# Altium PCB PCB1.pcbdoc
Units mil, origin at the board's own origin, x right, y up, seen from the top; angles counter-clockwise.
Board outline 2485 x 3040 mil, 2 copper layers (Top Layer, Bottom Layer); 17 components, 31 nets, 146 pads, 1 vias.
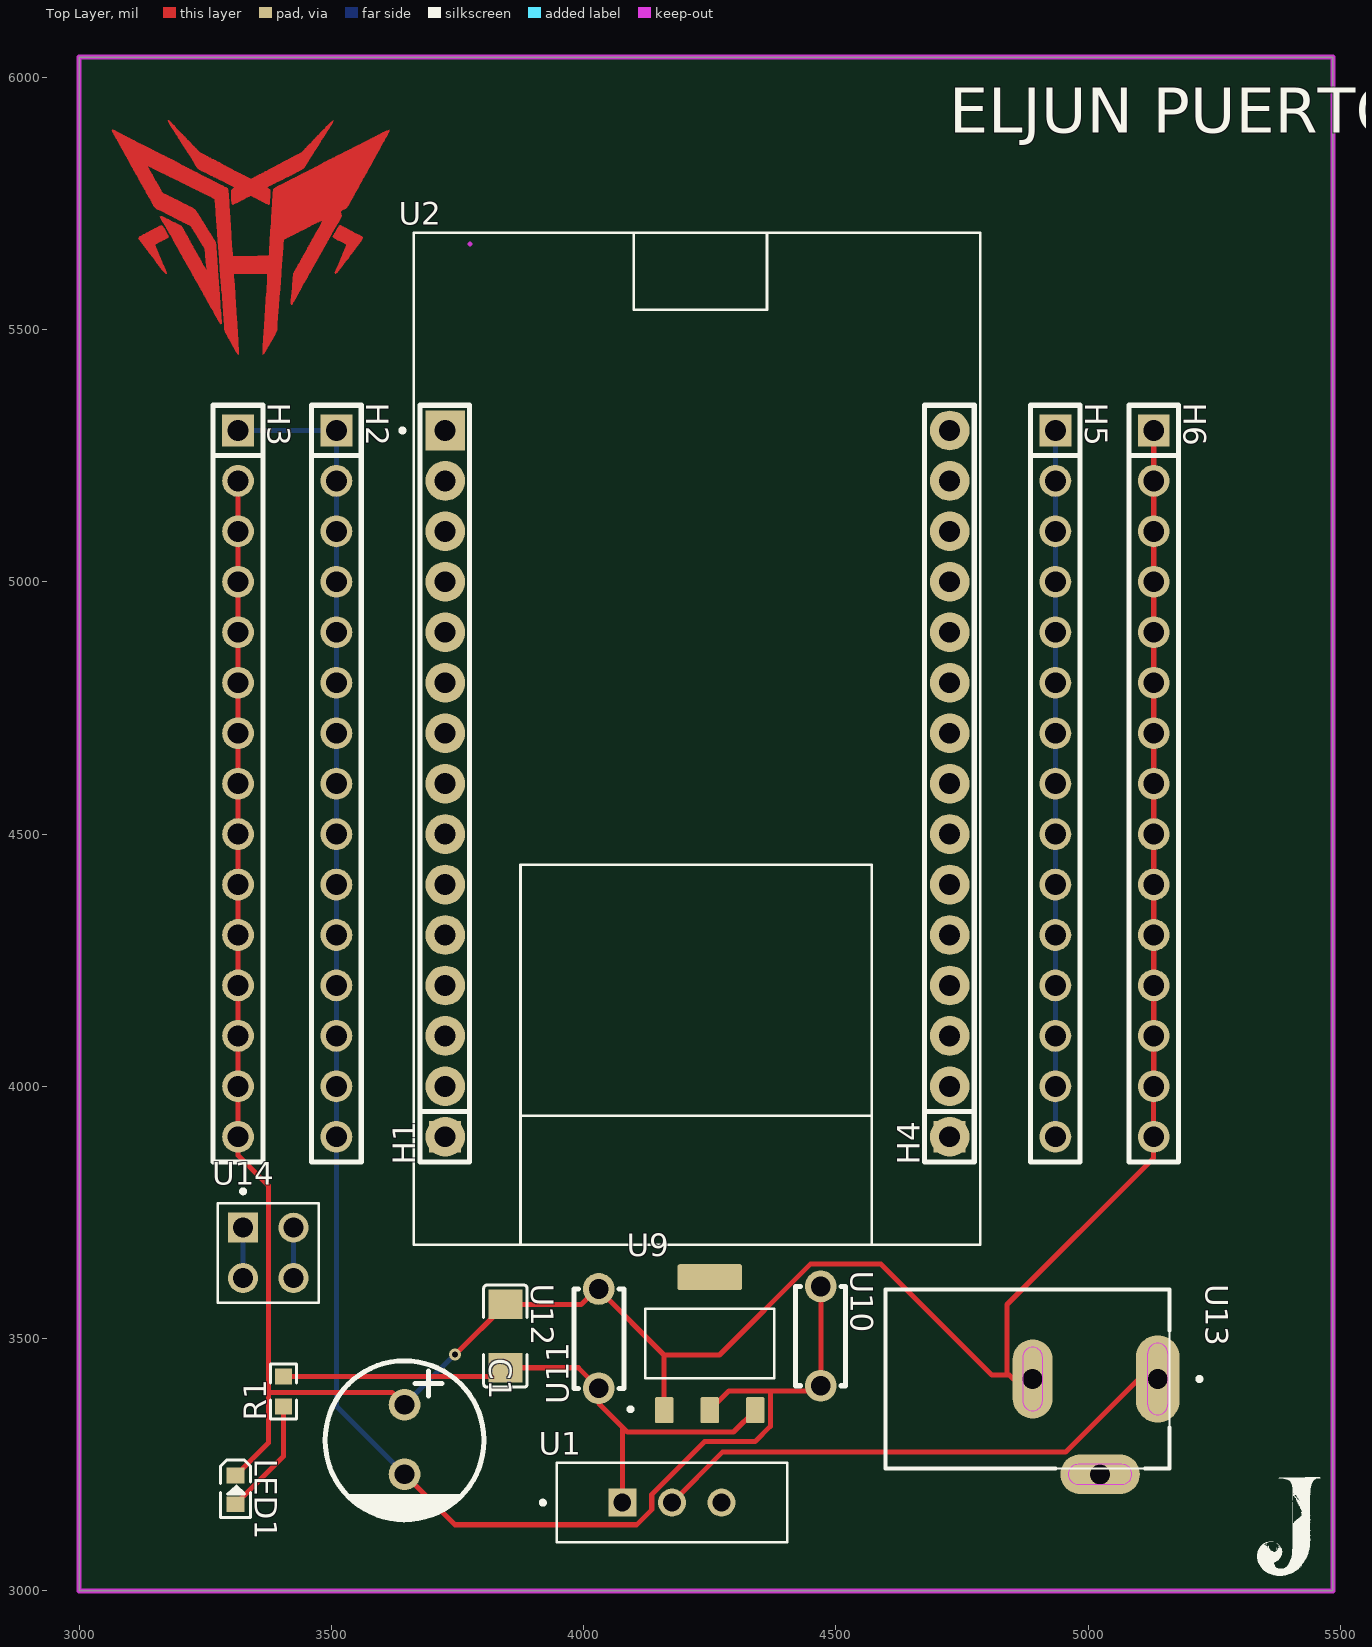
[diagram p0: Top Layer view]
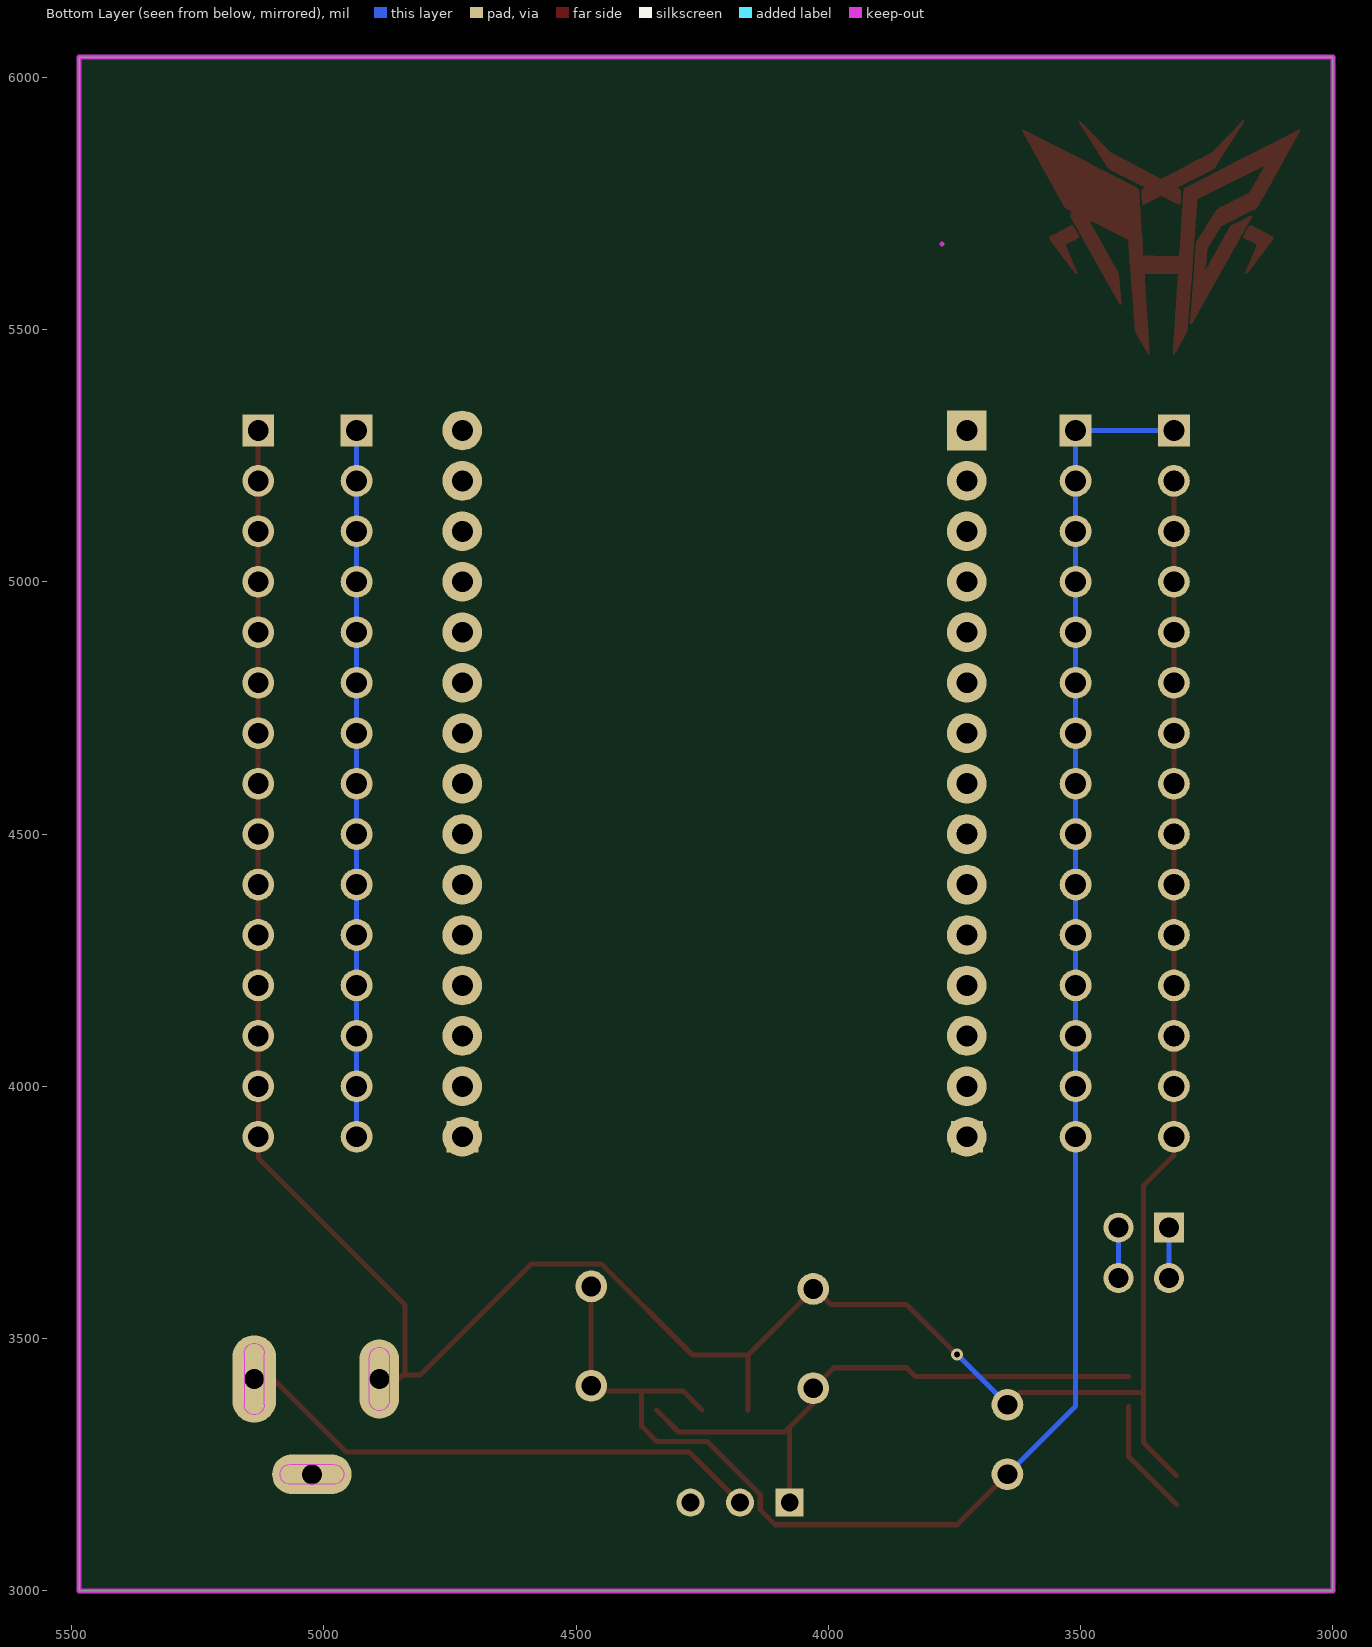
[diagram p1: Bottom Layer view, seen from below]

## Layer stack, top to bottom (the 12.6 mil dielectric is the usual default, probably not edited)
Top Layer: signal copper (thickness not stored)
Dielectric: dielectric 12.6, FR-4, Dk 4.8
Bottom Layer: signal copper (thickness not stored)

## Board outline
3000,6040 5485,6040 5485,3000 3000,3000

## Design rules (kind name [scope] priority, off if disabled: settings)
BoardOutlineClearance copperThickness1oz [All] p0: genericclearance=10 ignorepadtopadclearanceinfootprint=FALSE except(0: Arc-SplitContinuation Track-SplitContinuation SMDPad-SplitContinuation THPad-SplitContinuation Via-SplitContinuation Fill-SplitContinuation Poly-SplitContinuation Region-SplitContinuation Text-SplitContinuation; 6: Track-CutoutEdge SMDPad-CutoutEdge THPad-CutoutEdge Via-CutoutEdge Region-CutoutEdge; 11.8: Track-OutlineEdge SMDPad-OutlineEdge THPad-OutlineEdge Via-OutlineEdge Fill-OutlineEdge Region-OutlineEdge Poly-OutlineEdge Text-OutlineEdge Fill-CutoutEdge)
BoardOutlineClearance copperThickness2oz [All] p0: genericclearance=10 ignorepadtopadclearanceinfootprint=FALSE except(0: Arc-SplitContinuation Track-SplitContinuation SMDPad-SplitContinuation THPad-SplitContinuation Via-SplitContinuation Fill-SplitContinuation Poly-SplitContinuation Region-SplitContinuation Text-SplitContinuation; 6: Track-CutoutEdge SMDPad-CutoutEdge THPad-CutoutEdge Via-CutoutEdge Region-CutoutEdge; 11.8: Track-OutlineEdge SMDPad-OutlineEdge THPad-OutlineEdge Via-OutlineEdge Fill-OutlineEdge Region-OutlineEdge Poly-OutlineEdge Text-OutlineEdge Fill-CutoutEdge)
Clearance copperThickness1oz [(InNet('+5V') OR InNet('GND') OR InNet('EN') OR InNet('VP') OR InNet('VN') OR InNet('D2') OR InNet('D4') OR InNet('D5') OR InNet('D12') OR InNet('D14') OR InNet('D15') OR InNet('D18') OR InNet('D19') OR InNet('D21') OR InNet('+3V3') OR InNet('RX0') OR InNet('TX0') OR InNet('RX2') OR InNet('TX2') OR InNet('D22') OR InNet('D23') OR InNet('D25') OR InNet('D26') OR InNet('D27') OR InNet('D32') OR InNet('D33') OR InNet('D35') OR InNet('D34') OR InNet('$1N2884') OR InNet('VCC') OR InNet('$1N2361'))] p1: gap=7 ignorepadtopadclearanceinfootprint=FALSE except(4: Track-Track; 6: Track-SMDPad SMDPad-SMDPad Track-THPad SMDPad-THPad THPad-THPad Track-Via SMDPad-Via THPad-Via Via-Via SMDPad-Fill THPad-Fill Via-Fill Fill-Fill Track-Region SMDPad-Region THPad-Region Via-Region Region-Region Track-Poly SMDPad-Poly THPad-Poly Via-Poly Fill-Poly Region-Poly Poly-Poly Track-Text SMDPad-Text THPad-Text Via-Text Fill-Text Region-Text Poly-Text Text-Text; 6.9: Track-Hole SMDPad-Hole THPad-Hole Via-Hole Fill-Hole Region-Hole Poly-Hole Text-Hole Sheet-Hole; 11.8: Track-Fill Fill-Region Track-Sheet SMDPad-Sheet THPad-Sheet Via-Sheet Fill-Sheet Region-Sheet Poly-Sheet Text-Sheet)
Clearance copperThickness2oz [All] p1: gap=7 ignorepadtopadclearanceinfootprint=FALSE except(6: Track-SMDPad SMDPad-SMDPad Track-THPad SMDPad-THPad THPad-THPad Track-Via SMDPad-Via THPad-Via Via-Via SMDPad-Fill THPad-Fill Via-Fill Fill-Fill Track-Region SMDPad-Region THPad-Region Via-Region Region-Region Track-Poly SMDPad-Poly THPad-Poly Via-Poly Fill-Poly Region-Poly Poly-Poly Track-Text SMDPad-Text THPad-Text Via-Text Fill-Text Region-Text Poly-Text Text-Text; 6.9: Track-Hole SMDPad-Hole THPad-Hole Via-Hole Fill-Hole Region-Hole Poly-Hole Text-Hole Sheet-Hole; 8: Track-Track; 11.8: Track-Fill Fill-Region Track-Sheet SMDPad-Sheet THPad-Sheet Via-Sheet Fill-Sheet Region-Sheet Poly-Sheet Text-Sheet)
DiffPairsRouting differentialPair [All] p1: maxuncoupledlength=10 minlimit=6 maxlimit=6 mostfreqgap=6 toplayer_minwidth=5 toplayer_prefwidth=10 toplayer_maxwidth=100 bottomlayer_minwidth=5 bottomlayer_prefwidth=10 bottomlayer_maxwidth=100
PasteMaskExpansion pasteMaskExpansion [All] p1: expansion=0
PlaneConnect innerPlane [All] p1: planeconnectstyle=Relief reliefexpansion=20 reliefentries=4 reliefconductorwidth=10 reliefairgap=10
PolygonConnect copperRegion [All] p1: connectstyle=Relief reliefentries=4 reliefconductorwidth=10 polygonreliefangle="90 Angle" airgapwidth=10
RoutingVias viaSize [All] p1: viastyle="Through Hole" holewidth=12.0078 minholewidth=11.811 maxholewidth=248.0314 width=24.0158 minwidth=19.685 maxwidth=393.7008
SolderMaskExpansion solderMaskExpansion [All] p1: useseparateexpansions=TRUE expansion=2 expansionbottom=2
Width copperThickness1oz [All] p1: maxlimit=100 minlimit=5 preferedwidth=10
Width copperThickness2oz [All] p1: maxlimit=100 minlimit=8 preferedwidth=10

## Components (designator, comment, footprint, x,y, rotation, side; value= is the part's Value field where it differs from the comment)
C1 "100uF" CAP-TH_BD8.0-P3.50-D0.6-FD_1 3645,3300 r270 top
H1 "HDR-M_2.54_1x15P" HDR-TH_15P-P2.54-V-M 3725,4600 r90 top
H2 "HDR-M_2.54_1x15P" HDR-TH_15P-P2.54-V-M 3510,4600 r270 top
H3 "HDR-M_2.54_1x15P" HDR-TH_15P-P2.54-V-M 3315,4600 r270 top
H4 "HDR-M_2.54_1x15P" HDR-TH_15P-P2.54-V-M 4725,4600 r90 top
H5 "HDR-M_2.54_1x15P" HDR-TH_15P-P2.54-V-M 4935,4600 r270 top
H6 "HDR-M_2.54_1x15P" HDR-TH_15P-P2.54-V-M 5130,4600 r270 top
LED1 "19-217/BHC-ZL1M2RY/3T" LED0603-FD_BLUE 3310,3200 r270 top
R1 "Res_0603" R0603 3405,3395 r90 top
U1 "MINI-SPDT-SW" SW_MINI-SPDT-SW 4175,3175 r0 top
U2 "ESP32-DEVKIT-V1" MODULE_ESP32_DEVKIT_V1 4225.64,4689.15 r0 top
U9 "AMS1117-5.0" SOT229P700X180-4N 4250,3490 r0 top
U10 "100nF" CAP-TH_L5.0-W2.5-P5.00-D1.0 4470,3505 r270 top
U11 "100nF" CAP-TH_L5.0-W2.5-P5.00-D1.0 4030,3500 r90 top
U12 "10nF" C1206 3845,3505 r270 top
U13 "DCJ200-10-A-XX-K_REVA" GCT_DCJ200-10-A-XX-K_REVA 4880,3420 r270 top
U14 "826656-2" TE_826656-2 3375,3670 r0 top

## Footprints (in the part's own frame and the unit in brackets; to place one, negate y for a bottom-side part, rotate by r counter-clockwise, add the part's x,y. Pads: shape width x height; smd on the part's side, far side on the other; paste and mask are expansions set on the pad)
C1206 [mm]
  rect 1.485x1.728 smd: 1(-1.593,0) 2(1.593,0)
  silkscreen extent -2.56,-1.09 2.56,1.09
CAP-TH_BD8.0-P3.50-D0.6-FD_1 [mm]
  round 1.6 hole 1: 1(-1.75,0) 2(1.75,0)
  silkscreen extent -3.96,-4 4.04,4
CAP-TH_L5.0-W2.5-P5.00-D1.0 [mm]
  round 1.6 hole 1: 1(-2.5,0) 2(2.5,0)
  silkscreen extent -2.5,-1.27 2.5,1.25
GCT_DCJ200-10-A-XX-K_REVA [mm]
  oval 4.4x2.2 hole 1: 1(0,6.55)
  oval 4x2 hole 1: 2(0,0.25)
  oval 2x4 hole 1: 3(4.8,3.65)
  Board Outline Layer lines w0.003: 1.1,-0.25 -1.1,-0.25 ; 1.1,-0.25 -1.1,-0.25 ; 1.1,-0.25 ccw(c1.1,0.25) 1.6,0.25 ; 1.1,-0.25 ccw(c1.1,0.25) 1.6,0.25 ; -1.1,-0.25 cw(c-1.1,0.25) -1.6,0.25 ; -1.1,-0.25 cw(c-1.1,0.25) -1.6,0.25 ; 1.6,0.25 ccw(c1.1,0.25) 1.1,0.75 ; 1.6,0.25 ccw(c1.1,0.25) 1.1,0.75 ; -1.6,0.25 cw(c-1.1,0.25) -1.1,0.75 ; -1.6,0.25 cw(c-1.1,0.25) -1.1,0.75 ; 1.1,0.75 -1.1,0.75 ; 1.1,0.75 -1.1,0.75 ; 4.8,2.05 cw(c4.8,2.55) 4.3,2.55 ; 4.8,2.05 cw(c4.8,2.55) 4.3,2.55 ; 4.8,2.05 ccw(c4.8,2.55) 5.3,2.55 ; 4.8,2.05 ccw(c4.8,2.55) 5.3,2.55 ; 5.3,2.55 5.3,4.75 ; 5.3,2.55 5.3,4.75 ; 4.3,2.55 4.3,4.75 ; 4.3,2.55 4.3,4.75 ; 5.3,4.75 ccw(c4.8,4.75) 4.8,5.25 ; 5.3,4.75 ccw(c4.8,4.75) 4.8,5.25 ; 4.3,4.75 cw(c4.8,4.75) 4.8,5.25 ; 4.3,4.75 cw(c4.8,4.75) 4.8,5.25 ; 1.3,6.05 ccw(c1.3,6.55) 1.8,6.55 ; 1.3,6.05 ccw(c1.3,6.55) 1.8,6.55 ; 1.3,6.05 -1.3,6.05 ; 1.3,6.05 -1.3,6.05 ; -1.3,6.05 cw(c-1.3,6.55) -1.8,6.55 ; -1.3,6.05 cw(c-1.3,6.55) -1.8,6.55 ; 1.8,6.55 ccw(c1.3,6.55) 1.3,7.05 ; 1.8,6.55 ccw(c1.3,6.55) 1.3,7.05 ; -1.8,6.55 cw(c-1.3,6.55) -1.3,7.05 ; -1.8,6.55 cw(c-1.3,6.55) -1.3,7.05 ; 1.3,7.05 -1.3,7.05 ; 1.3,7.05 -1.3,7.05
  silkscreen extent -4.5,-7.15 4.5,8.75
HDR-TH_15P-P2.54-V-M [mm]
  rect 1.6x1.6 hole 1.05: 1(-17.78,0)
  round 1.6 hole 1.05: 2(-15.24,0) 3(-12.7,0) 4(-10.16,0) 5(-7.62,0) 6(-5.08,0) 7(-2.54,0) 8(0,0) 9(2.54,0) 10(5.08,0) 11(7.62,0) 12(10.16,0) 13(12.7,0) 14(15.24,0) 15(17.78,0)
  silkscreen extent -19.05,-1.25 19.05,1.25
LED0603-FD_BLUE [mm]
  rect 0.8x0.9 smd: 1(-0.72,0) 2(0.72,0)
  silkscreen extent -1.5,-0.76 1.38,0.76
MODULE_ESP32_DEVKIT_V1 [mm]
  rect 2x2 hole 1.02: 1(-12.7,15.515)
  round 2 hole 1.02: 2(-12.7,12.975) 3(-12.7,10.435) 4(-12.7,7.895) 5(-12.7,5.355) 6(-12.7,2.815) 7(-12.7,0.275) 8(-12.7,-2.265) 9(-12.7,-4.805) 10(-12.7,-7.345) 11(-12.7,-9.885) 12(-12.7,-12.425) 13(-12.7,-14.965) 14(-12.7,-17.505) 15(-12.7,-20.045) 16(12.7,-20.045) 17(12.7,-17.505) 18(12.7,-14.965) 19(12.7,-12.425) 20(12.7,-9.885) 21(12.7,-7.345) 22(12.7,-4.805) 23(12.7,-2.265) 24(12.7,0.275) 25(12.7,2.815) 26(12.7,5.355) 27(12.7,7.895) 28(12.7,10.435) 29(12.7,12.975) 30(12.7,15.515)
  silkscreen extent -14.95,-25.48 14.23,25.48
R0603 [mil]
  rect 31.75x34.02 smd: 1(-29.66,0) 2(29.66,0)
  silkscreen extent -55,-26 55,26
SOT229P700X180-4N [mm]
  rrect15% 0.93x1.31 smd: 1(-2.29,-3.345) 2(0,-3.345) 3(2.29,-3.345)
  rrect15% 3.24x1.31 smd: 4(0,3.345)
  silkscreen extent -4.09,-3.4 3.25,1.75
SW_MINI-SPDT-SW [mm]
  rect 1.408x1.408 hole 0.9: 1(-2.5,0)
  round 1.408 hole 0.9: 2(0,0) 3(2.5,0)
  silkscreen extent -6.6,-2 5.8,2
TE_826656-2 [mm]
  rect 1.508x1.508 hole 1: 1(-1.27,1.27)
  round 1.508 hole 1: 2(1.27,1.27) 3(-1.27,-1.27) 4(1.27,-1.27)
  silkscreen extent -2.54,-2.5 2.54,3.2

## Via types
v1: diameter 24.02, hole 12.01, Top Layer to Bottom Layer, 1 vias

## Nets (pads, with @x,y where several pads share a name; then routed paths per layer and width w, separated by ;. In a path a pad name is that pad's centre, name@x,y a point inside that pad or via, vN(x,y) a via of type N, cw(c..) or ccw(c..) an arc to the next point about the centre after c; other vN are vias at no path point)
$1N2361: U1.2 U13.1 | length 1064.4
  Top Layer w10: U1.2 4275,3275 4955,3275 5100,3420 U13.1
$1N2884: LED1.2 R1.1 | length 233
  Top Layer w10: LED1.2 3405,3266.66 R1.1
+3V3: H4.1 H5.1 H5.2 H5.3 H5.4 H5.5 H5.6 H5.7 H5.8 H5.9 H5.10 H5.11 H5.12 H5.13 H5.14 H5.15 U2.1 | length 1400
  Bottom Layer w10: H5.15 H5.14 H5.13 H5.12 H5.11 H5.10 H5.9 H5.8 H5.7 H5.6 H5.5 H5.4 H5.3 H5.2 H5.1
+5V: C1.2 H1.1 H2.1 H2.2 H2.3 H2.4 H2.5 H2.6 H2.7 H2.8 H2.9 H2.10 H2.11 H2.12 H2.13 H2.14 H2.15 H3.1 U2.30 U9.2 U10.1 U10.2 | length 3691.4
  Top Layer w10: C1.2 3745,3131.1 4105,3131.1 4135,3161.1 4135,3191.1 4240,3296.1 4340,3296.1 4370,3326.1 4370,3396.1 ; U9.2 4287.79,3396.1 4370,3396.1 ; U10.1 U10.2 4459.52,3396.1 4370,3396.1
  Bottom Layer w10: H3.1 H2.1 H2.2 H2.3 H2.4 H2.5 H2.6 H2.7 H2.8 H2.9 H2.10 H2.11 H2.12 H2.13 H2.14 H2.15 3510,3366.1 C1.2
D2: H1.6 U2.4
D4: H1.7 U2.5
D5: H1.8 U2.8
D12: H1.9 H1.10 U2.27 U2.28
D14: H1.11 U2.26
D15: H1.12 U2.3
D18: H1.13 U2.9
D19: H1.14 U2.10
D21: H1.15 U2.11
D22: H4.7 U2.14 U14.1 U14.3 | length 100
  Bottom Layer w10: U14.3 U14.1
D23: H4.8 U2.15 U14.2 U14.4 | length 100
  Bottom Layer w10: U14.4 U14.2
D25: H4.9 U2.23
D26: H4.10 U2.24
D27: H4.11 U2.25
D32: H4.12 U2.21
D33: H4.13 U2.22
D34: H4.15 U2.19
D35: H4.14 U2.20
EN: H1.3 U2.16
GND: C1.1 H1.2 H3.2 H3.3 H3.4 H3.5 H3.6 H3.7 H3.8 H3.9 H3.10 H3.11 H3.12 H3.13 H3.14 H3.15 H4.2 H6.1 H6.2 H6.3 H6.4 H6.5 H6.6 H6.7 H6.8 H6.9 H6.10 H6.11 H6.12 H6.13 H6.14 H6.15 LED1.1 U9.1 U11.2 U12.1 U13.2 | length 5971.7
  Top Layer w10: LED1.1 3375,3293.34 3375,3393.34 ; H3.2 H3.3 H3.4 H3.5 H3.6 H3.7 H3.8 H3.9 H3.10 H3.11 H3.12 H3.13 H3.14 H3.15 3315,3863.34 3375,3803.34 3375,3393.34 ; C1.1 3620.55,3393.34 3375,3393.34 ; v1(3745,3468.9) 3746.2,3468.9 U12.1 3995,3567.7 4025,3597.7 U11.2@4029.28,3597.7 ; U11.2 U11.2@4029.28,3597.7 ; U9.1 4159.27,3358.87 4159.27,3467.7 ; U13.2 4851.57,3420 4843.88,3427.7 4839.27,3427.7 ; H6.15 H6.15@5129.27,3897.7 ; H6.1 H6.2 H6.3 H6.4 H6.5 H6.6 H6.7 H6.8 H6.9 H6.10 H6.11 H6.12 H6.13 H6.14 5129.27,3999.28 H6.15@5129.27,3897.7 ; U11.2@4029.28,3597.7 4159.27,3467.7 ; 4159.27,3467.7 4269.27,3467.7 4449.27,3647.7 4589.27,3647.7 4809.27,3427.7 4839.27,3427.7 ; 4839.27,3427.7 4839.27,3567.7 5129.27,3857.7 H6.15@5129.27,3897.7
  Bottom Layer w10: C1.1 v1(3745,3468.9)
RX0: H4.3 U2.12
RX2: H4.5 U2.6
TX0: H4.4 U2.13
TX2: H4.6 U2.7
VCC: R1.2 U1.1 U9.3 U11.1 U12.2 | length 1180.7
  Top Layer w10: R1.2 3827.36,3424.66 U12.2 3989.28,3442.3 U11.1 4030,3371.57 4076.57,3325 ; U1.1 4076.57,3325 ; U9.3 4296.85,3315 4086.57,3315 4076.57,3325
VN: H1.5 U2.18
VP: H1.4 U2.17
pads on no net: U1.3 U2.2 U2.29 U9.4 U13.3

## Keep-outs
Board Outline Layer:
  lines w10: 3000,3000 5485,3000 5485,6040 3000,6040 3000,3000 ; 3775,5669.9 3775.1,5669.9 3775.1,5670 3775,5670 3775,5669.9

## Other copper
Top Layer:
  region: 2205 vertices and 1 holes, not listed, extent 3065,5450 3615,5896.24
  region: 3507.47,5610.15 3507.12,5612.86 3508.77,5617.59 3509.08,5618.29 3509.41,5619.16 3511.38,5624.11 3512.88,5626.87 3513.41,5627.61 3513.86,5628.72 3514.2,5629.71 3514.5,5630.11 3514.75,5630.45 3514.98,5631.26 3515.3,5632.32 3515.8,5633.27 3516.24,5634.06 3516.42,5634.71 3516.61,5635.4 3517.06,5636.27 3517.51,5637.17 3517.7,5637.93 3517.89,5638.67 3518.34,5639.51 3518.79,5640.31 3518.98,5640.97 3519.17,5641.66 3519.62,5642.53 3520.07,5643.43 3520.26,5644.21 3520.39,5644.83 3520.72,5645.36 3521.1,5646.01 3521.38,5646.94 3521.65,5647.86 3522.02,5648.51 3522.39,5649.15 3522.66,5650.07 3522.93,5651 3523.3,5651.64 3523.67,5652.3 3523.95,5653.26 3524.22,5654.14 3524.57,5654.63 3524.93,5655.15 3525.19,5656.13 3525.47,5657.19 3525.86,5657.91 3526.2,5658.46 3526.33,5659.12 3526.51,5659.86 3526.94,5660.6 3527.43,5661.47 3527.76,5662.53 3528.05,5663.51 3528.43,5664.18 3528.76,5664.71 3528.89,5665.33 3529.07,5666.09 3529.51,5666.97 3529.89,5668.3 3528.82,5669.06 3528.1,5669.41 3527.59,5669.88 3527.15,5670.26 3526.61,5670.42 3525.05,5670.97 3521.7,5672.78 3517.13,5675.14 3512.1,5677.48 3509.62,5678.65 3507.24,5679.93 3505.42,5680.94 3504.29,5681.49 3503.14,5683.79 3503.93,5687.06 3504.55,5688.07 3505.24,5689.41 3505.88,5690.63 3506.35,5691.36 3507.38,5693.09 3509.37,5696.68 3511.64,5700.56 3512.96,5702.03 3513.6,5702.51 3513.86,5703.09 3514.16,5704 3514.88,5705.28 3517.03,5706.86 3518.97,5706.24 3519.56,5705.76 3520.44,5705.42 3521.3,5705.09 3521.88,5704.64 3522.45,5704.19 3523.32,5703.85 3524.18,5703.53 3524.75,5703.09 3525.26,5702.65 3526,5702.32 3527,5701.93 3528.13,5701.32 3529.15,5700.78 3529.88,5700.56 3530.37,5700.39 3530.8,5699.98 3531.41,5699.5 3532.31,5699.15 3533.14,5698.81 3533.59,5698.36 3533.9,5697.98 3534.42,5697.82 3535.3,5697.59 3536.47,5697.04 3537.85,5696.25 3539.23,5695.47 3540.28,5694.92 3540.87,5694.69 3541.49,5694.45 3542.61,5693.87 3544.02,5693.08 3545.36,5692.35 3550.01,5689.91 3554.93,5687.45 3556.64,5686.6 3557.65,5686.05 3558.63,5685.47 3560.27,5684.54 3562.44,5682.86 3562.52,5680.54 3560.14,5676.53 3554.92,5669.79 3552.09,5666.21 3550.64,5664.27 3549.02,5661.9 3546.28,5658.17 3542.9,5653.72 3539.4,5649.23 3537.87,5647.25 3536.72,5645.69 3533.17,5640.82 3528.73,5635.01 3521.7,5625.94 3518.05,5620.98 3515.03,5616.78 3512.96,5614.46 3512.31,5613.97 3511.19,5612.8 3508.67,5610.15
  region: 3173.23,5610.62 3171.7,5610.24 3169.59,5612.16 3168.31,5613.76 3167.45,5614.8 3164.24,5618.69 3159.28,5625 3154.2,5631.64 3150.59,5636.53 3148.66,5639.09 3145.59,5643.02 3139.3,5651.1 3136.06,5655.69 3134.51,5657.94 3132.43,5660.68 3125.15,5670.02 3119.93,5677.08 3118.55,5678.97 3117.74,5679.93 3117.45,5680.47 3117.34,5681.33 3120.5,5684.94 3125.44,5687.25 3125.84,5687.36 3126.12,5687.62 3126.6,5688.01 3127.49,5688.45 3128.98,5689.17 3130.87,5690.24 3132.54,5691.17 3133.52,5691.56 3134.21,5691.78 3135.18,5692.32 3136.49,5693.11 3137.96,5693.92 3139.33,5694.66 3140.36,5695.27 3141.27,5695.72 3142.35,5696.06 3143.3,5696.42 3143.91,5696.88 3144.26,5697.27 3144.58,5697.43 3146.54,5698.35 3149.31,5699.96 3150.23,5700.41 3151.29,5700.76 3152.17,5701.11 3152.64,5701.58 3152.92,5701.96 3153.35,5702.12 3155.03,5702.78 3158.01,5704.51 3159.03,5705.04 3159.82,5705.26 3160.48,5705.48 3161.19,5706.02 3164.11,5706.61 3165.94,5704.67 3166.3,5704 3167.14,5703.03 3168.13,5701.87 3168.81,5700.72 3169.5,5699.35 3170.49,5697.67 3171.34,5696.19 3171.7,5695.32 3172.03,5694.56 3172.82,5693.35 3173.61,5692.19 3173.94,5691.56 3175.1,5689.37 3176.84,5686.54 3177.33,5682.99 3175.18,5680.99 3174.47,5680.72 3173.2,5680.07 3169.32,5677.97 3166.9,5676.9 3165.28,5676.2 3163.86,5675.5 3158.74,5672.7 3156.83,5671.99 3156.21,5671.82 3155.72,5671.42 3155.24,5670.94 3154.64,5670.6 3151.05,5668.2 3151.41,5665.51 3151.77,5664.88 3152.05,5663.94 3152.33,5662.96 3152.69,5662.21 3153.04,5661.48 3153.32,5660.57 3153.59,5659.77 3153.94,5659.33 3154.29,5658.79 3154.56,5657.77 3154.83,5656.75 3155.2,5656.21 3155.56,5655.67 3155.84,5654.64 3156.11,5653.62 3156.48,5653.08 3156.84,5652.53 3157.12,5651.51 3157.39,5650.49 3157.76,5649.95 3158.12,5649.39 3158.4,5648.34 3158.64,5647.35 3158.9,5646.94 3159.21,5646.51 3159.57,5645.47 3159.91,5644.38 3160.18,5643.81 3160.68,5642.81 3161.58,5640.68 3162.5,5638.44 3163.04,5637.16 3163.53,5636 3164.32,5634.03 3165.11,5632.06 3165.59,5630.9 3165.94,5630.05 3166.42,5628.85 3166.91,5627.89 3167.27,5627.6 3167.56,5627.49 3167.86,5626.91 3168.18,5626.1 3168.49,5625.42 3169,5624.26 3169.79,5622.29 3170.56,5620.32 3171.02,5619.16 3171.4,5618.26 3171.96,5616.93 3172.45,5615.6 3172.66,5614.72 3172.8,5614.19 3173.14,5613.68 3173.6,5612.18
  region: 603 vertices and 0 holes, not listed, extent 3175.92,5747.16 3503.84,5915

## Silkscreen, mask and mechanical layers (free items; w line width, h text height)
Top Silkscreen Layer:
  drawing of 95 lines, arcs and shapes, not listed
  text "ELJUN PUERTOS" at 4725,5890.08 h90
